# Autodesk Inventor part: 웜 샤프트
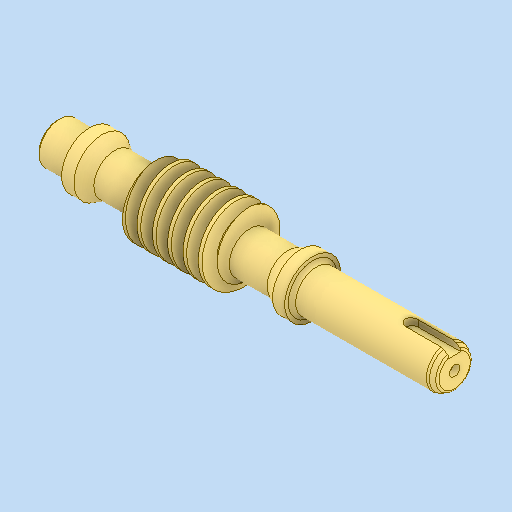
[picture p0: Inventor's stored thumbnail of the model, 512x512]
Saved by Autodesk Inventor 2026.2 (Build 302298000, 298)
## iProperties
Created: 2026-01
Part Number: 웜 샤프트
Material: 강철, 합금
Document SubType Name: Modeling
Designer: PC2-07
Density: 7.73 g/cm^3
Appearance: 기본값
Author: jhkim
Sending System: Autodesk Inventor 2026
Preprocessor: ST-DEVELOPER v20.1
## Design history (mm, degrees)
feature "솔리드1"
node "솔리드2"
